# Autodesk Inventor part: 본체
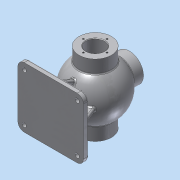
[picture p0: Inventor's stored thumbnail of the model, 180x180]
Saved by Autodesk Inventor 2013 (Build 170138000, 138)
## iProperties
Created: 2018-06
Part Number: 본체
Material: 알루미늄 6061
Document SubType Name: Modeling
Designer: Administrator
Density: 2.71 g/cm^3
Mass: 1509.57 g
Surface Area: 1153.7 cm^2
Volume: 557.037 cm^3
Author: Administrator
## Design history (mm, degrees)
sketch "스케치1"
  geometry: L1 (0, 53)-(0, -53); A1 r 53 centre (0, 0) between (0, -53) and (0, 53); A2 r 43 centre (0, 0) between (0, -43) and (0, 43); 1 further point
  constraints: 4 point on circle, 2 centre point, 2 coincident, 2 end point, 2 point on line, 1 midpoint, 1 vertical
  dimensions: "d0" = 106 diameter of A1; "d1" = 86 diameter of A2
revolve "회전1" sketch "스케치1" stored, may be unused: angle "d2" = 90 deg
node "작업 평면1"
sketch "스케치2"
  geometry: C1 r 31 at (0, 0); 1 further point
  constraints: 1 centre point, 1 coincident
  dimensions: "d4" = 62 diameter of C1
extrude "돌출1" join sketch "스케치2" stored distance "d5" = 10; taper "d6" = 0 deg
hole "구멍1" diameter "d9" = 35; stored, may be unused: countersink angle "d13" = 90 deg, drill point angle "d15" = 118 deg; dims "d7" = 10, "d8" = 10, "d10" = 6, "d11" = 4, "d12" = 2, "d14" = 8
sketch "스케치3"
  geometry: C1 r 17.5 at (0, 0) reference; 1 further point
  constraints: 1 vertical alignment
  dimensions: "d16" = 22.5 distance of C1.centre point (0, 22.5)
hole "구멍2" sketch "스케치3" at (0, 22.5) diameter "d17" = 3.242; stored, may be unused: countersink angle "d21" = 90 deg, drill point angle "d23" = 118 deg; dims "d18" = 12, "d19" = 4, "d20" = 2, "d22" = 15
node "작업 평면2"
sketch "스케치4"
  geometry: C1 r 27 at (0, 0); 1 further point
  constraints: 1 centre point, 1 coincident
  dimensions: "d28" = 54 diameter of C1
extrude "돌출2" join sketch "스케치4" stored distance "d29" = 10; taper "d30" = 0 deg
hole "구멍4" diameter "d42" = 26; stored, may be unused: countersink angle "d46" = 90 deg, drill point angle "d48" = 0 deg; dims "d40" = 10, "d41" = 10, "d43" = 9, "d44" = 4, "d45" = 2, "d47" = 11
sketch "스케치5"
  geometry: C1 r 13 at (0, 0) reference; 1 further point
  constraints: 1 horizontal alignment
  dimensions: "d49" = 20 distance of C1.centre point (-20, 0)
hole "구멍5" sketch "스케치5" at (-20, 0) diameter "d50" = 3.242; stored, may be unused: countersink angle "d54" = 90 deg, drill point angle "d56" = 118 deg; dims "d51" = 9, "d52" = 4, "d53" = 2, "d55" = 11
sketch "스케치6"
  geometry: C1 r 17.5 at (0, 0) reference; 1 further point
  constraints: 1 vertical alignment
  dimensions: "d60" = 24 distance of C1.centre point (0, 24)
hole "구멍6" sketch "스케치6" at (0, 24) diameter "d61" = 3.242; stored, may be unused: countersink angle "d65" = 90 deg, drill point angle "d67" = 118 deg; dims "d62" = 16, "d63" = 4, "d64" = 2, "d66" = 19
node "작업 평면3"
sketch "스케치7"
  geometry: L1 (-62.5, -57.5)-(62.5, -57.5); L2 (62.5, -57.5)-(62.5, 57.5); L3 (62.5, 57.5)-(-62.5, 57.5); L4 (-62.5, 57.5)-(-62.5, -57.5); L5 (-62.5, -57.5)-(62.5, 57.5); L6 (62.5, -57.5)-(-62.5, 57.5); 1 further point
  constraints: 12 end point, 2 midpoint, 2 parallel, 1 horizontal, 1 perpendicular
  dimensions: "d72" = 125 distance of L3.end L2.end; "d73" = 115 distance of L2.end L1.end
extrude "돌출3" join sketch "스케치7" distance "d74" = 10; taper "d75" = 0 deg
sketch "스케치12"
  geometry: L1 (-62.5, 57.5)-(-62.5, -57.5) reference; L2 (52.5, -4)-(-52.5, -4); L3 (-52.5, -4)-(-52.5, 4); L4 (-52.5, 4)-(52.5, 4); L5 (52.5, 4)-(52.5, -4); L6 (52.5, -4)-(-52.5, 4); L7 (-52.5, -4)-(52.5, 4); 1 further point
  constraints: 12 end point, 2 midpoint, 2 parallel, 1 horizontal, 1 perpendicular
  dimensions: "d85" = 8 distance of L2.end L3.end; "d87" = 10 distance between parallel lines of L1 L3
extrude "돌출5" join sketch "스케치12" stored distance "d88" = 8; taper "d89" = 0 deg
feature "면 기울기1" dims angle "d90" = 22 deg
sketch "스케치13"
  geometry: L1 (-75, -47.5)-(-40.891, -33.719); L2 (-75, -57.5)-(-75, 57.5) reference; L3 (-85, -57.5)-(-75, -57.5) reference; A1 r 53 centre (0, 0) between (31, -42.988) and (-31, -42.988) reference; 1 further point
  constraints: 2 end point, 1 point on circle, 1 point on line
  dimensions: "d91" = 10 distance from line of L3 L1.start; "d92" = 112 deg angle of L2 L1
feature "리브1" sketch "스케치13" dims "d93" = 1, "d94" = 8, "d95" = 0, "d96" = 0, "d97" = 1, "d98" = 1
node "작업 평면4"
sketch "스케치14"
  geometry: C1 r 18.5 at (0, 0); 1 further point
  constraints: 1 centre point, 1 coincident
  dimensions: "d100" = 37 diameter of C1
extrude "돌출6" cut sketch "스케치14" distance "d101" = 1.75; taper "d102" = 0 deg
chamfer "모따기1" distance "d103" = 1; stored, may be unused: second distance "d104" = 2, angle "d105" = 45 deg
fillet "모깎기1" dims "d106" = 12
sketch "스케치15"
  geometry: A1 r 12 centre (50.5, 45.5) between (62.5, 45.5) and (50.5, 57.5) reference; 2 further points
  constraints: 1 coincident
hole "구멍7" sketch "스케치15" at (50.5, 45.5) diameter "d107" = 8; stored, may be unused: countersink angle "d111" = 90 deg, drill point angle "d113" = 0 deg; dims "d108" = 16, "d109" = 12, "d110" = 3, "d112" = 10
fillet "모깎기2" dims "d120" = 3
fillet "모깎기3" dims "d121" = 3
fillet "모깎기4" dims "d122" = 3
node "작업 평면5"
sketch "스케치16"
  geometry: L1 (-65, -27)-(-47.286, -27) reference; L2 (-65, -27)-(-65, 27) reference; 2 further points
  constraints: 1 other
  dimensions: "d124" = 27 distance from line of point (-55, 0) L1; "d125" = 10 distance from line of point (-55, 0) L2
feature "엠보싱1" sketch "스케치16" dims "d0" = 106, "d1" = 86, "d19" = 4, "d126" = 0.5, "d127" = 0
node "솔리드1"
pattern_circular "원형 패턴1" dims angle "d25" = 360 deg
pattern_circular "원형 패턴2" dims angle "d58" = 360 deg
mirror "대칭2"
pattern_circular "원형 패턴3" dims angle "d69" = 360 deg
mirror "대칭4"
pattern_linear "직사각형 패턴1" dims "d116" = 91, "d119" = 101
other parameters: "d3" = 68, "d27" = 65, "d71" = -85, "d99" = -52, "d123" = -27
